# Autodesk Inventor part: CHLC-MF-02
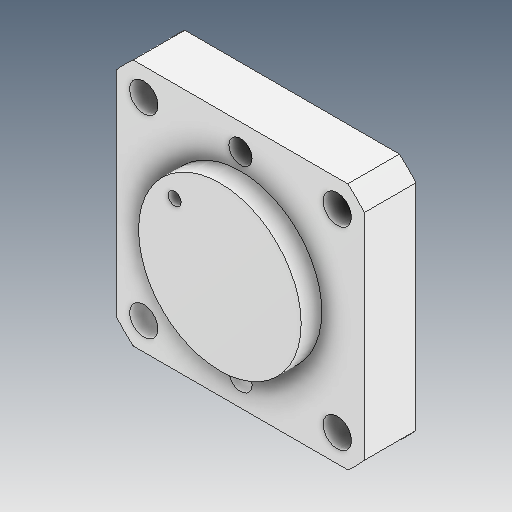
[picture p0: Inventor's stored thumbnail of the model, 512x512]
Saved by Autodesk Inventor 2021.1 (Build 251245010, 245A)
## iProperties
Created: 2021-05
Part Number: CHLC-MF-02
Material: Ogólny
Document SubType Name: Modeling
Designer: user
Density: 1 g/cm^3
Appearance: Domyślna
Author: user
Revision Number: ÈÎºÎ
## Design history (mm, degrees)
feature "ÊäÈë3"
node "Bryła1"
